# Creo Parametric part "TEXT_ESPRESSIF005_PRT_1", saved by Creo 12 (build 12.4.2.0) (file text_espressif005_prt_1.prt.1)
Units: Custom; MM, KILOGRAM, SECS

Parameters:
  PTC_WM_ITERATION = "0"
  PTC_WM_VERSION = "-.0"
  PTC_WM_LIFECYCLE_STATE = "In Work"
  PTC_WM_LIFECYCLE = "MO_CADDocument"
  PTC_WM_CREATED_BY = "Maximilian Roepper (Z0017RMS: MO)"
  PTC_WM_CREATED_ON = "18-Sep-26 11:36:42 AM"
  PTC_WM_MODIFIED_BY = "Maximilian Roepper (Z0017RMS: MO)"
  PTC_WM_MODIFIED_ON = "18-Sep-26 11:36:46 AM"
  PDMLINKNUMBER = "PDM000071454835"
  PTC_WM_NAME = "text_espressif005_prt_1.prt"
  PTC_WM_NUMBER = "PDM000071454835"

Other parameters: WEIGHT, WEIGHT_FACTOR, WEIGHT_ADD, _MASS_TEMP, _DIFF_TEMP, MC_ERRORS, SUPPLIER

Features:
  1. coordinate system
  2. datum plane "PRT_YZ"
  3. datum plane "PRT_XY"
  4. datum plane "PRT_XZ"
  5. coordinate system
  6. datum axis
  7. datum axis
  8. datum axis
  9. coordinate system
  10. imported feature
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
Other named items: PRT, SIEMENS_MO, DRW_VIEW_ORG, PRT_X, PRT_Y, PRT_Z, CS0, ROUGH_GROB

Layers: 00_STD_CSYS-KSYS, 01_STD_PLANES-EBENEN, 02_STD_AXES-ACHSEN, 03_STD_CSYS-KSYS, 24_IMPORT_FEAT-IMPORT_KE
